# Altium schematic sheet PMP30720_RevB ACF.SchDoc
size 431 x 279 mm; Date: Not shown in title block; ApprovedBy: Not shown in title block; CheckedBy: Not shown in title block; Author: Not shown in title block; CompanyName: Not shown in title block; Engineer: Not shown in title block; Organization: Not shown in title block; Address1: Not shown in title block; Address2: Not shown in title block; Address3: Not shown in title block; Address4: Not shown in title block; DocumentNumber: 1; Revision: Use project parameter SCH_Rev; SheetNumber: 1; SheetTotal: 1; PageSetup: Record=PageOptions¦CenterHorizontal=True¦CenterVertical=True¦PrintScale=1.00¦XCorrection=1.00¦YCorrection=1.00¦PrintKind=0¦BorderSize=5000000¦LeftOffset=0¦BottomOffset=0¦Orientation=2¦PaperLength=1000¦PaperWidth=1000¦Scale=100¦PaperSource=15¦PrintQuality=600¦MediaType=1¦DitherType=10¦PaperKind=Letter¦PrintScaleMode=1
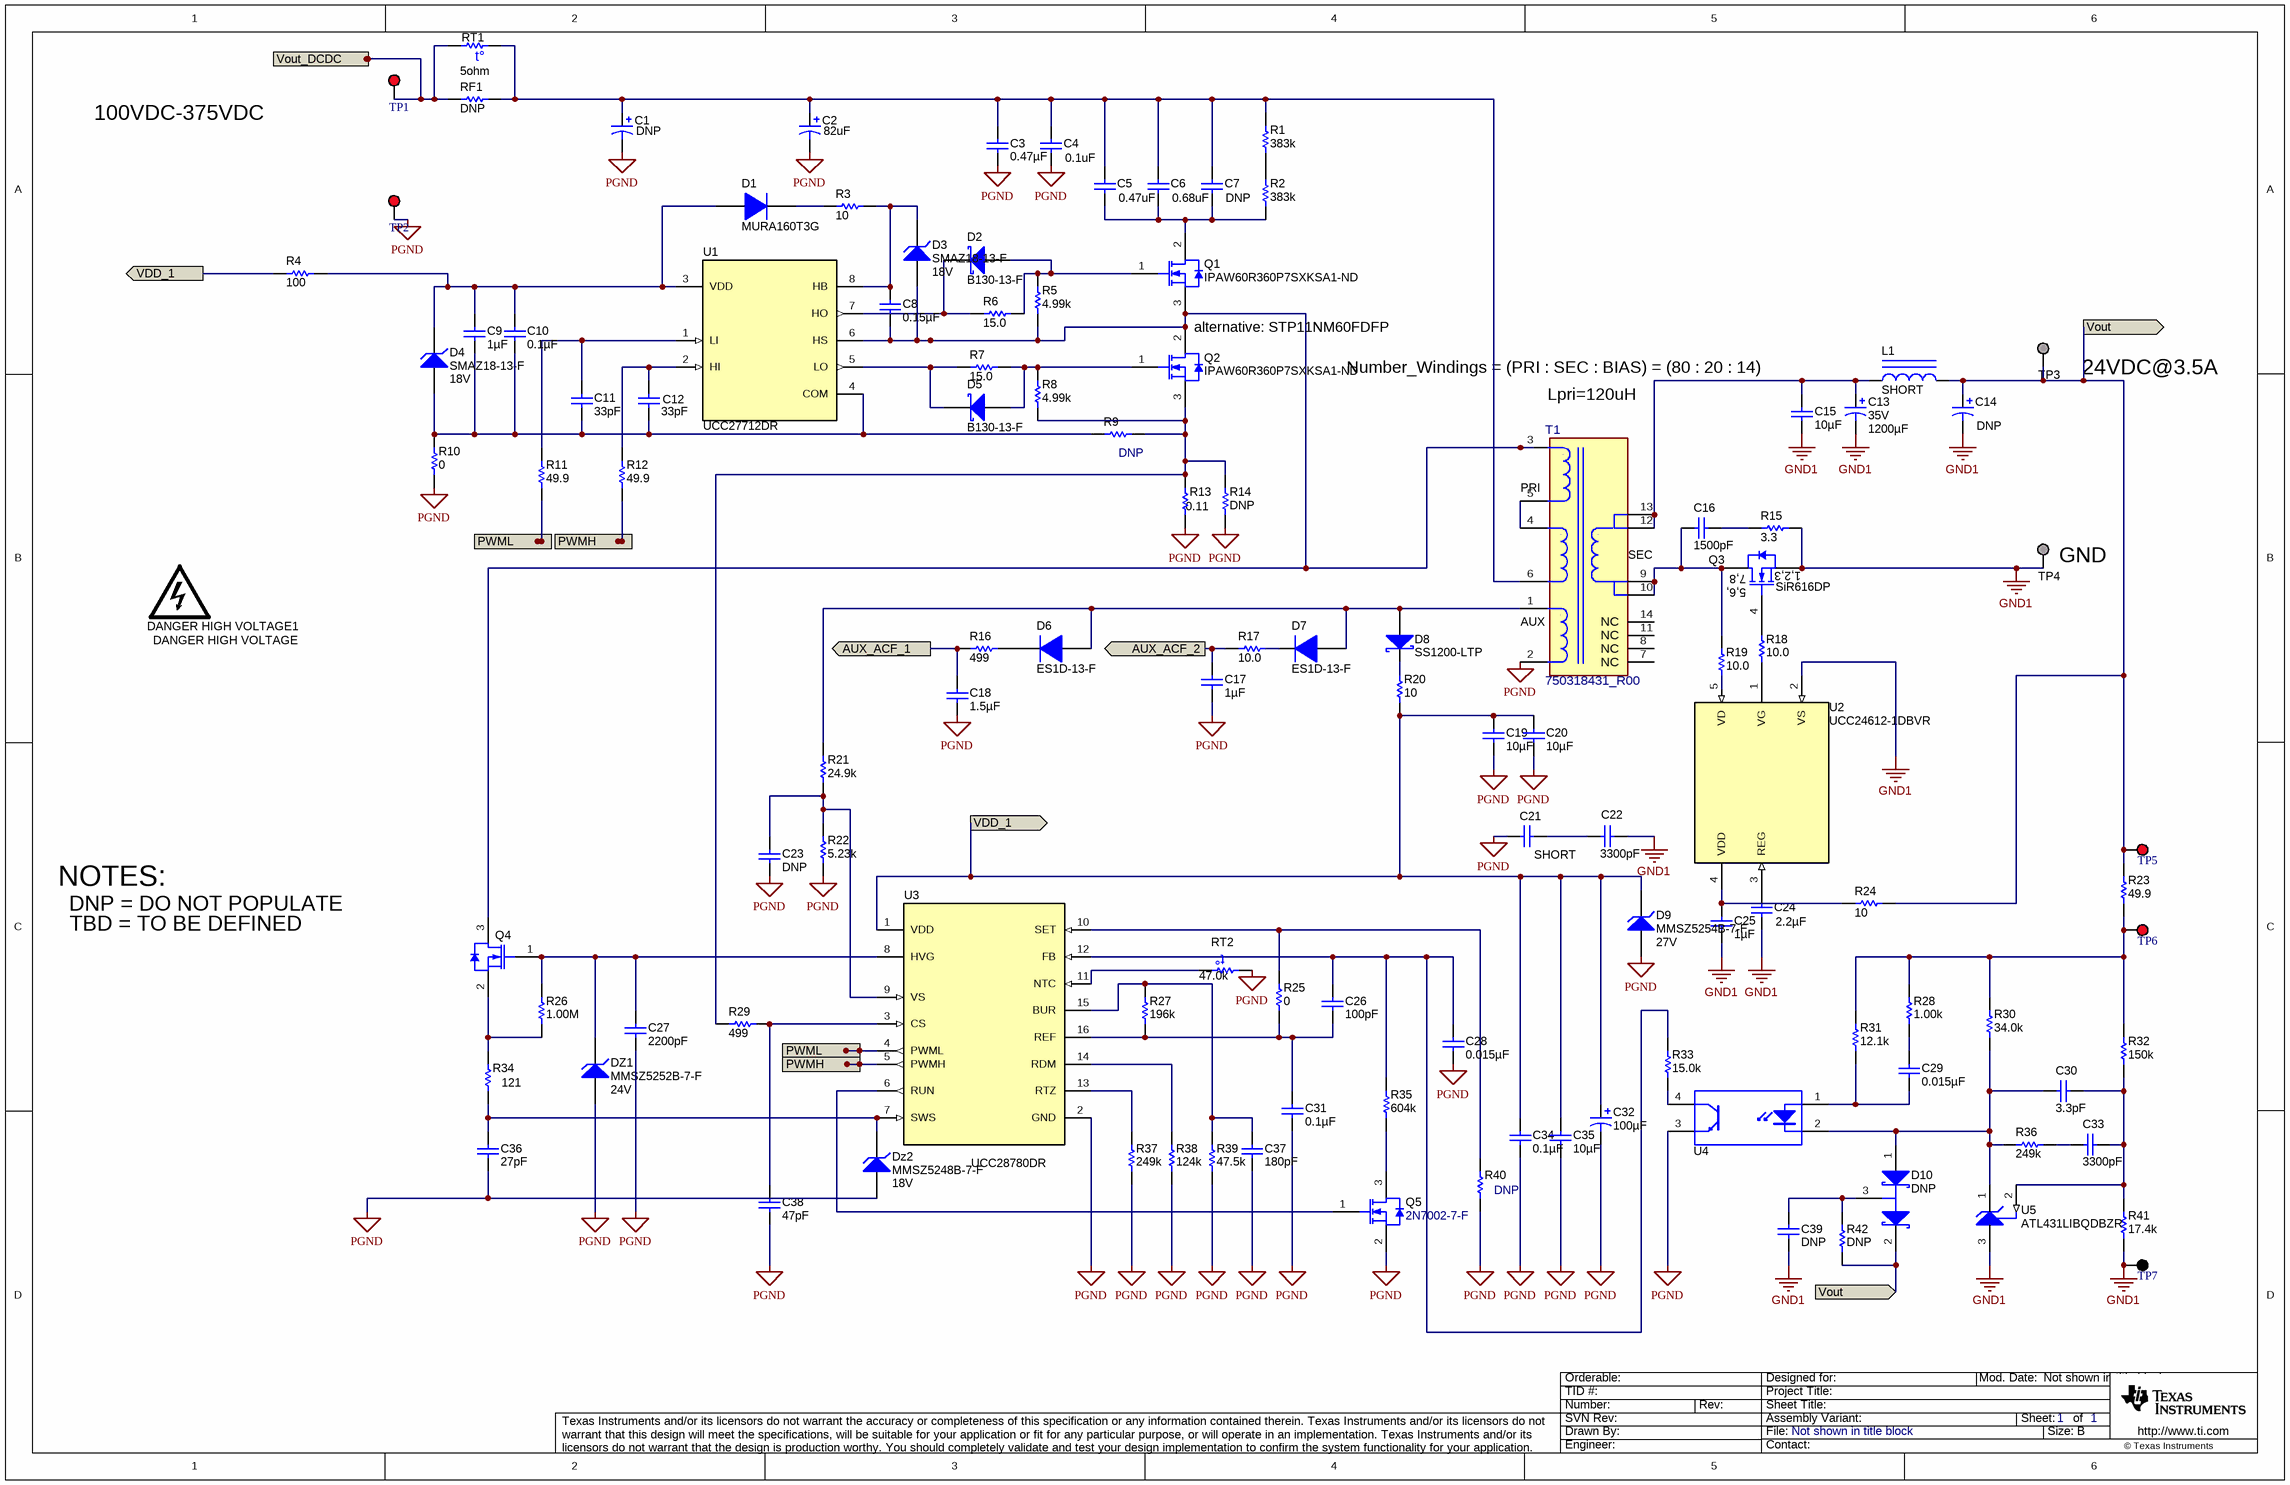
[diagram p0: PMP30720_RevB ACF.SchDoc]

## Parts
C1  value DNP  [CAPPR7.5-18x31.5]  (hidden comment: 450BXW82MEFR18X30)
C2  value 82uF  [CAPPR7.5-18x31.5]  (hidden comment: 450BXW82MEFR18X30)
C3  ValueDisplayed: 0.47µF  [1812_254]  (hidden comment: 1812Y5000474KXTWS2)
C4  ValueDisplayed: 0.1uF  [1206_190]  (hidden comment: C3216X7T2W104K160AA)
C5  value 0.47uF  [2220]  (hidden comment: GRM55DR72E474KW01L)
C6  value 0.68uF  [2220]  (hidden comment: DNP)
C7  value DNP  [2220]  (hidden comment: GRM55DR72E684KW01L)
C8  ValueDisplayed: 0.15µF  [0805_HV]  (hidden comment: C0805C154K5RACTU)
C9  ValueDisplayed: 1µF  [0805_HV]  (hidden comment: GRM21BR71H105KA12L)
C10  ValueDisplayed: 0.1µF  [0805_HV]  (hidden comment: GRM21BR71H104KA01L)
C11  ValueDisplayed: 33pF  [0603]  (hidden comment: GRM1885C1H330JA01D)
C12  ValueDisplayed: 33pF  [0603]  (hidden comment: GRM1885C1H330JA01D)
C13  VDC_V: 35V  ValueDisplayed: 1200µF  [Panasonic_1250x3000]  (hidden comment: EEU-FM1V122L)
C14  DNP  [CAPPR5-12.5x25]
C15  ValueDisplayed: 10µF  [1210_270]  (hidden comment: GRM32ER71H106KA12L)
C16  ValueDisplayed: 1500pF  [1206]  (hidden comment: GRM31BR72J152KW01L)
C17  ValueDisplayed: 1µF  [1206]  (hidden comment: GRM31MR71H105KA88L)
C18  ValueDisplayed: 1.5µF  [1206_180]  (hidden comment: C3216X7R1H155K160AB)
C19  ValueDisplayed: 10µF  [1210_280]  (hidden comment: C3225X7R1H106M250AC)
C20  ValueDisplayed: 10µF  [1210_280]  (hidden comment: C3225X7R1H106M250AC)
C21  SHORT  [KX_1000x700]
C22  ValueDisplayed: 3300pF  [KX_1000x700]  (hidden comment: DE1E3KX332MN4AP01F)
C23  DNP  [0603]
C24  ValueDisplayed: 2.2µF  [0805_HV]  (hidden comment: C2012X7R1H225K125AC)
C25  ValueDisplayed: 1µF  [0805_HV]  (hidden comment: GRM21BR71H105KA12L)
C26  ValueDisplayed: 100pF  [0603]  (hidden comment: GRM1885C1H101JA01D)
C27  ValueDisplayed: 2200pF  [0603]  (hidden comment: GRM188R71H222KA01D)
C28  ValueDisplayed: 0.015µF  [0603]  (hidden comment: GRM188R71H153KA01D)
C29  ValueDisplayed: 0.015µF  [0603]  (hidden comment: GRM188R71H153KA01D)
C30  ValueDisplayed: 3.3pF  [0603]  (hidden comment: 06035A3R3CAT2A)
C31  ValueDisplayed: 0.1µF  [0805_HV]  (hidden comment: GRM21BR71H104KA01L)
C32  ValueDisplayed: 100µF  [SM_RADIAL_D8]  (hidden comment: EEE-FK1V101XP)
C33  ValueDisplayed: 3300pF  [0603]  (hidden comment: GRM188R71H332KA01D)
C34  ValueDisplayed: 0.1µF  [0805_HV]  (hidden comment: GRM21BR71H104KA01L)
C35  ValueDisplayed: 10µF  [1210_270]  (hidden comment: GRM32ER71H106MA12)
C36  ValueDisplayed: 27pF  [0603]  (hidden comment: GRM1885C1H270JA01D)
C37  ValueDisplayed: 180pF  [0805_HV]  (hidden comment: GRM2165C1H181JA01D)
C38  ValueDisplayed: 47pF  [0603]  (hidden comment: GRM1885C1H470JA01D)
C39  DNP  [1206_180]
D1  MURA160T3G  [SMA]
D2  B130-13-F  [SMA]
D3  SMAZ18-13-F  value 18V  [SMA]
D4  SMAZ18-13-F  value 18V  [SMA]
D5  B130-13-F  [SMA]
D6  ES1D-13-F  [SMA]
D7  ES1D-13-F  [SMA]
D8  SS1200-LTP  [SMA]
D9  MMSZ5254B-7-F  value 27V  [SOD-123]
D10  DNP  [SOT-23]
DANGER_HIGH_VOLTAGE1  DANGER HIGH VOLTAGE  [IEC_HighVoltage_Small]  (no BOM)
DZ1  MMSZ5252B-7-F  value 24V  [SOD-123]
Dz2  MMSZ5248B-7-F  value 18V  [SOD-123]
L1  ValueDisplayed: SHORT  [WE-TI_5075]  (hidden comment: 7447462010)
Q1  IPAW60R360P7SXKSA1-ND  [TO-220AB]
Q2  IPAW60R360P7SXKSA1-ND  [TO-220AB]
Q3  PartNumber: SiR616DP  [PG-TDSON-8]  (hidden comment: SiR616)
Q4  BSS126 H6906  [SOT-23]  (value not drawn)
Q5  2N7002-7-F  [SOT-23]
R1  ValueDisplayed: 383k  [1206]  (hidden comment: CRCW1206383KFKEA)
R2  ValueDisplayed: 383k  [1206]  (hidden comment: CRCW1206383KFKEA)
R3  ValueDisplayed: 10  [0805_HV]  (hidden comment: CRCW080510R0JNEA)
R4  ValueDisplayed: 100  [1206]  (hidden comment: CRCW1206100RJNEA)
R5  ValueDisplayed: 4.99k  [0805_HV]  (hidden comment: CRCW08054K99FKEA)
R6  ValueDisplayed: 15.0  [0805_HV]  (hidden comment: CRCW080515R0FKEA)
R7  ValueDisplayed: 15.0  [0805_HV]  (hidden comment: CRCW080515R0FKEA)
R8  ValueDisplayed: 4.99k  [0805_HV]  (hidden comment: CRCW08054K99FKEA)
R9  DNP  [0805]
R10  ValueDisplayed: 0  [1206]  (hidden comment: CRCW12060000Z0EA)
R11  ValueDisplayed: 49.9  [0603]  (hidden comment: CRCW060349R9FKEA)
R12  ValueDisplayed: 49.9  [0603]  (hidden comment: CRCW060349R9FKEA)
R13  value 0.11  [1206]  (hidden comment: ERJ-8RSJR12V)
R14  DNP  [1206]
R15  ValueDisplayed: 3.3  [2512]  (hidden comment: CRCW25123R30JNEG)
R16  ValueDisplayed: 499  [1206]  (hidden comment: CRCW1206499RFKEA)
R17  ValueDisplayed: 10.0  [1206]  (hidden comment: CRCW120610R0FKEA)
R18  ValueDisplayed: 10.0  [0805_HV]  (hidden comment: CRCW080510R0FKEA)
R19  ValueDisplayed: 10.0  [0603]  (hidden comment: CRCW060310R0FKEA)
R20  ValueDisplayed: 10  [0805_HV]  (hidden comment: CRCW080510R0JNEA)
R21  ValueDisplayed: 24.9k  [0603]  (hidden comment: CRCW060324K9FKEA)
R22  ValueDisplayed: 5.23k  [0603]  (hidden comment: CRCW06035K23FKEA)
R23  ValueDisplayed: 49.9  [0603]  (hidden comment: CRCW060349R9FKEA)
R24  ValueDisplayed: 10  [0805_HV]  (hidden comment: CRCW080510R0JNEA)
R25  ValueDisplayed: 0  [0603]  (hidden comment: CRCW06030000Z0EA)
R26  ValueDisplayed: 1.00M  [0603]  (hidden comment: CRCW06031M00FKEA)
R27  ValueDisplayed: 196k  [0603]  (hidden comment: CRCW0603196KFKEA)
R28  ValueDisplayed: 1.00k  [0603]  (hidden comment: CRCW06031K00FKEA)
R29  ValueDisplayed: 499  [0603]  (hidden comment: CRCW0603499RFKEA)
R30  ValueDisplayed: 34.0k  [0603]  (hidden comment: CRCW060334K0FKEA)
R31  ValueDisplayed: 12.1k  [0603]  (hidden comment: RC0603FR-0712K1L)
R32  ValueDisplayed: 150k  [0603]  (hidden comment: CRCW0603150KFKEA)
R33  ValueDisplayed: 15.0k  [0603]  (hidden comment: CRCW060315K0FKEA)
R34  value 121  [0603]  (hidden comment: CRCW0603121RFKEA)
R35  ValueDisplayed: 604k  [0603]  (hidden comment: CRCW0603604KFKEA)
R36  ValueDisplayed: 249k  [0603]  (hidden comment: CRCW0603249KFKEA)
R37  ValueDisplayed: 249k  [0603]  (hidden comment: CRCW0603249KFKEA)
R38  ValueDisplayed: 124k  [0603]  (hidden comment: CRCW0603124KFKEA)
R39  ValueDisplayed: 47.5k  [0603]  (hidden comment: CRCW060347K5FKEA)
R40  DNP  [0603_HV]
R41  ValueDisplayed: 17.4k  [0603]  (hidden comment: CRCW060317K4FKEA)
R42  DNP  [0805_HV]
RF1  DNP  [2512]
RT1  value 5ohm  [S237]  (hidden comment: B57464S0509M000)
RT2  value 47.0k  [0603]  (hidden comment: NCP18WB473F10RB)
T1  750318431_R00  [FP-750318431_R00_PTH_14-MFG]
TP1  5000  [Keystone5000]  (value not drawn)
TP2  5000  [Keystone5000]  (value not drawn)
TP3  Suggest using a net name here  [Keystone1503-2]  (value not drawn)
TP4  Suggest using a net name here  [Keystone1503-2]  (value not drawn)
TP5  5000  [Keystone5000]  (value not drawn)
TP6  5000  [Keystone5000]  (value not drawn)
TP7  5001  [Keystone5001]  (value not drawn)
U1  UCC27712DR  [D0008A_N]
U2  UCC24612-1DBVR  [DBV0005A_N]
U3  UCC28780DR  [D0016A_N]
U4  FOD817AS  [N04C]  (value not drawn)
U5  ATL431LIBQDBZR  [DBZ0003A_N]

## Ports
AUX_ACF_1 (out), AUX_ACF_2 (out), PWMH (in), PWMH (out), PWML (in), PWML (out), VDD_1 (out), Vout (in), Vout (out), Vout_DCDC (in)

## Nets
GND1: C13.2(-) C14.2(-) C15.2 C22.1 C24.2 C25.2 C39.2 Q3.1(S) Q3.2(S) Q3.3(S) R15.2 R41.1 TP4.1 TP7.1 U2.2(VS) U5.3(ANODE)
PGND: C1.2(-) C2.2(-) C3.2 C4.2 C17.2 C18.2 C19.2 C20.2 C21.2 C23.2 C27.1 C28.2 C31.2 C32.2(-) C34.2 C35.2 C36.2 C37.2 C38.2 D9.2(A) DZ1.2(A) Dz2.2(A) Q5.2(S) R10.1 R13.1 R14.1 R22.1 R37.1 R38.1 R39.1 R40.2 RT2.1 T1.2 TP2.1 U3.2(GND) U4.3(E)
AUX_ACF_1: C18.1 R16.1 ; port AUX_ACF_1
AUX_ACF_2: C17.1 R17.1 ; port AUX_ACF_2
PWMH: U3.5(PWMH) ; port PWMH
PWML: U3.4(PWML) ; port PWML
VDD_1: C19.1 C20.1 C32.1(+) C34.1 C35.1 D9.1(K) R4.1 R20.1 U3.1(VDD) ; port VDD_1
Vout: C14.1(+) D10.2(K) L1.2 R23.2 R24.2 R42.1 TP3.1 TP5.1 ; port Vout
Vout_DCDC: RF1.1 RT1.1 TP1.1 ; port Vout_DCDC
NetC1_1: C1.1(+) C2.1(+) C3.1 C4.1 C5.1 C6.1 C7.1 R1.2 RF1.2 RT1.2 T1.6
NetC5_2: C5.2 C6.2 C7.2 Q1.2(D) R2.1
NetC8_1: C8.1 D3.1(K) R3.1 U1.8(HB)
NetC8_2: C8.2 D3.2(A) Q1.3(S) Q2.2(D) Q4.3(D) R5.1 T1.3 U1.6(HS)
NetC9_1: C9.1 C10.1 D1.2(A) D4.1(K) R4.2 U1.3(VDD)
NetC9_2: C9.2 C10.2 C11.2 C12.2 D4.2(A) R9.1 R10.2 U1.4(COM)
NetC11_1: C11.1 R11.2 U1.1(LI)
NetC12_1: C12.1 R12.2 U1.2(HI)
NetC13_1: C13.1(+) C15.1 L1.1 T1.12 T1.13
NetC16_1: C16.1 R15.1
NetC16_2: C16.2 Q3.5(D) Q3.6(D) Q3.7(D) Q3.8(D) Q3.9(D) R19.2 T1.9 T1.10
NetC21_1: C21.1 C22.2
NetC23_1: C23.1 R21.1 R22.2 U3.9(VS)
NetC24_1: C24.1 U2.3(REG)
NetC25_1: C25.1 R24.1 U2.4(VDD)
NetC26_1: C26.1 C28.1 R33.2 R35.2 U3.12(FB)
NetC26_2: C26.2 C31.1 R25.1 R27.1 U3.16(REF)
NetC27_2: C27.2 DZ1.1(K) Q4.1(G) R26.2 U3.8(HVG)
NetC29_1: C29.1 R28.1
NetC29_2: C29.2 R31.1 U4.1(A)
NetC30_1: C30.1 C33.1 R32.1 R41.2 U5.2(REF)
NetC30_2: C30.2 D10.1(A) R30.1 R36.1 U4.2(K) U5.1(CATHODE)
NetC33_2: C33.2 R36.2
NetC36_1: C36.1 Dz2.1(K) R34.1 U3.7(SWS)
NetC37_1: C37.1 R27.2 R39.2 U3.15(BUR)
NetC38_1: C38.1 R29.2 U3.3(CS)
NetC39_1: C39.1 D10.3(C) R42.2
NetD1_1: D1.1(K) R3.2
NetD2_1: D2.1(K) R6.2 U1.7(HO)
NetD2_2: D2.2(A) Q1.1(G) R5.2 R6.1
NetD5_1: D5.1(K) R7.2 U1.5(LO)
NetD5_2: D5.2(A) Q2.1(G) R7.1 R8.2
NetD6_1: D6.1(K) R16.2
NetD6_2: D6.2(A) D7.2(A) D8.2(A) R21.2 T1.1
NetD7_1: D7.1(K) R17.2
NetD8_1: D8.1(K) R20.2
NetQ2_3: Q2.3(S) R8.1 R9.2 R13.2 R14.2 R29.1
NetQ3_4: Q3.4(G) R18.2
NetQ4_2: Q4.2(S) R26.1 R34.2
NetQ5_1: Q5.1(G) U3.6(RUN)
NetQ5_3: Q5.3(D) R35.1
NetR1_1: R1.1 R2.2
NetR18_1: R18.1 U2.1(VG)
NetR19_1: R19.1 U2.5(VD)
NetR23_1: R23.1 R28.2 R30.2 R31.2 R32.2 TP6.1
NetR25_2: R25.2 R40.1 U3.10(SET)
NetR33_1: R33.1 U4.4(C)
NetR37_2: R37.2 U3.13(RTZ)
NetR38_2: R38.2 U3.14(RDM)
NetRT2_2: RT2.2 U3.11(NTC)
NetT1_4: T1.4 T1.5

Not connected (* = marked no-connect by the designer): R11 1; R12 1; T1 7(NC) 8(NC) 11(NC) 14(NC)

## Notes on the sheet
- 100VDC-375VDC
- alternative: STP11NM60FDFP
- (near C15) Number_Windings = (PRI : SEC : BIAS) = (80 : 20 : 14)
- (near TP3) 24VDC@3.5A
- (near T1) Lpri=120uH
- (near T1) PRI
- (near T1) SEC
- (near TP4) GND
- (near T1) AUX
- NOTES:
- DNP = DO NOT POPULATE
- TBD = TO BE DEFINED

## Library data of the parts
C1 C2 = Capacitor_Polarized: CAP, [Technology], 82uF, 450V, +/-xx%, xxOhm ESR, [MountType]; Manufacturer: Used in BOM report; Polarized: Y; U/M: EA
C3 = 1812Y5000474KXTWS2: CAP, CERM, 0.47 µF, 500 V,+/- 10%, X7R, 1812; Manufacturer: Knowles Capacitors; Polarized: N; CompType: Capacitor; Value: 0.47uF; U/M: EA; Cap_F: 0.00000047; Tolerance_%: 10; VDC_V: 500; Value2: 500V; TaMin_C: -55; TaMax_C: 125; Cap_Case: 1812; SizeArea_mm2: 14.4; SizeAreaWB_mm2: 23.1; SizeX_mm: 4.5; SizeY_mm: 3.2; SizeZ_mm: 2.54; AEC Category: Q200; Green_Lifecycle: Not Set; Green_REACh: Incomplete
C4 = CMP-0008727-1: CAP, CERM, 0.1 uF, 450 V, +/- 10%, X7T, 1206_190; Manufacturer: TDK; TaMin_C: -55°C; Polarized: N; SizeAreaWB_mm2: 10.92; Value1: Unknown; U/M: EA; Value: 0.1uF; TaMax_C: 125°C; SizeZ_mm: 1.9; SizeX_mm: 3.2; SizeY_mm: 1.6; Cap_Case: 1206; Value2: 450V; SizeArea_mm2: 5.12; Cap_F: 100nF; AEC Category: Q200
C5 = GRM55DR72E474KW01L: CAP, CERM, 0.47 µF, 250 V,+/- 10%, X7R, 2220; Manufacturer: MuRata; Polarized: N; CompType: Capacitor; ValueDisplayed: 0.47µF; U/M: EA; Cap_F: 0.00000047; Tolerance_%: 10; VDC_V: 250; Value2: 250V; TaMin_C: -55; TaMax_C: 125; SizeArea_mm2: 28.5; SizeAreaWB_mm2: 53.9; SizeX_mm: 5.7; SizeY_mm: 5; SizeZ_mm: 1.35; AEC Category: Q200
C6 C7 = GRM55DR72E474KW01L: CAP, CERM, 0.68 µF, 250 V,+/- 10%, X7R, 2220; Manufacturer: MuRata; Polarized: N; CompType: Capacitor; U/M: EA; Cap_F: 0.00000047; Tolerance_%: 10; VDC_V: 250; Value2: 250V; TaMin_C: -55; TaMax_C: 125; SizeArea_mm2: 28.5; SizeAreaWB_mm2: 53.9; SizeX_mm: 5.7; SizeY_mm: 5; SizeZ_mm: 1.35; AEC Category: Q200
C8 = C0805C154K5RACTU: CAP, CERM, 0.15 µF, 50 V,+/- 10%, X7R, 0805; Manufacturer: Kemet; Polarized: N; CompType: Capacitor; Value: 0.15uF; U/M: EA; Cap_F: 0.00000015; Tolerance_%: 10; ESR_ohm: 0.054; Value1: 0.054 ohm; VDC_V: 50; Value2: 50V; IRMS_A: 2.09; TaMin_C: -55; TaMax_C: 125; Cap_Case: 0805; SizeArea_mm2: 2.5; SizeAreaWB_mm2: 6.75; SizeX_mm: 2; SizeY_mm: 1.25; SizeZ_mm: 1.45; AEC Category: Q200; Green_Lifecycle: Active; Green_REACh: Passed
C9 C25 = GRM21BR71H105KA12L: CAP, CERM, 1 µF, 50 V,+/- 10%, X7R, 0805; Manufacturer: MuRata; Polarized: N; CompType: Capacitor; Value: 1uF; U/M: EA; Cap_F: 0.000001; Tolerance_%: 10; VDC_V: 50; Value2: 50V; TaMin_C: -55; TaMax_C: 125; Cap_Case: 0805; SizeArea_mm2: 2.5; SizeAreaWB_mm2: 6.75; SizeX_mm: 2; SizeY_mm: 1.25; SizeZ_mm: 1.45; AEC Category: Q200; Green_Lifecycle: Active; Green_REACh: Passed
C10 C31 C34 = GRM21BR71H104KA01L: CAP, CERM, 0.1 µF, 50 V,+/- 10%, X7R, 0805; Manufacturer: MuRata; Polarized: N; CompType: Capacitor; Value: 0.1uF; U/M: EA; Cap_F: 0.0000001; Tolerance_%: 10; VDC_V: 50; Value2: 50V; TaMin_C: -55; TaMax_C: 125; Cap_Case: 0805; SizeArea_mm2: 2.5; SizeAreaWB_mm2: 6.75; SizeX_mm: 2; SizeY_mm: 1.25; SizeZ_mm: 1.45; AEC Category: Q200; Green_Lifecycle: Active; Green_REACh: Passed
C11 C12 = GRM1885C1H330JA01D: CAP, CERM, 33 pF, 50 V,+/- 5%, C0G/NP0, 0603; Manufacturer: MuRata; Polarized: N; CompType: Capacitor; Value: 33pF; U/M: EA; Cap_F: 0.000000000033; Tolerance_%: 5; VDC_V: 50; Value2: 50V; TaMin_C: -55; TaMax_C: 125; SizeArea_mm2: 1.28; SizeAreaWB_mm2: 4.68; SizeX_mm: 1.6; SizeY_mm: 0.8; SizeZ_mm: 1; AEC Category: Q200; Green_Lifecycle: Active; Green_REACh: Passed
C13 = CMP-0079558-1: CAP, AL, 1200 µF, 35 V, +/- 20%, TH; Manufacturer: Panasonic; Cap_F: 1.2mF; IRMS_A: 3.63A; SizeAreaWB_mm2: 210.25; SizeArea_mm2: 156.25; AEC Qualified: N; AEC Category: Q200; Value: 1200uF; TaMax_C: 105°C; SizeZ_mm: 32; Polarized: Y; TaMin_C: -40°C; SizeY_mm: 12.5; U/M: EA; CompType: Capacitor; Cap_Case: 12.5x30mm
C14 = Capacitor_Polarized: CAP, [Technology], xxxF, xxV, +/-xx%, xxOhm ESR, [MountType]; Manufacturer: Used in BOM report; Polarized: Y; U/M: EA
C15 = GRM32ER71H106KA12L: CAP, CERM, 10 µF, 50 V,+/- 10%, X7R, 1210; Manufacturer: MuRata; Polarized: N; CompType: Capacitor; Value: 10uF; U/M: EA; Cap_F: 0.00001; Tolerance_%: 10; VDC_V: 50; Value2: 50V; TaMin_C: -55; TaMax_C: 125; Cap_Case: 1210; SizeArea_mm2: 8; SizeAreaWB_mm2: 14.7; SizeX_mm: 3.2; SizeY_mm: 2.5; SizeZ_mm: 2.7; AEC Category: Q200; Green_Lifecycle: Active; Green_REACh: Passed
C16 = GRM31BR72J152KW01L: CAP, CERM, 1500 pF, 630 V,+/- 10%, X7R, 1206; Manufacturer: MuRata; Polarized: N; CompType: Capacitor; Value: 1500pF; U/M: EA; Cap_F: 0.0000000015; Tolerance_%: 10; VDC_V: 630; Value2: 630V; TaMin_C: -55; TaMax_C: 125; SizeArea_mm2: 5.12; SizeAreaWB_mm2: 10.92; SizeX_mm: 3.2; SizeY_mm: 1.6; SizeZ_mm: 1.35; AEC Category: Q200
C17 = GRM31MR71H105KA88L: CAP, CERM, 1 µF, 50 V,+/- 10%, X7R, 1206; Manufacturer: MuRata; Polarized: N; CompType: Capacitor; Value: 1uF; U/M: EA; Cap_F: 0.000001; Tolerance_%: 10; VDC_V: 50; Value2: 50V; TaMin_C: -55; TaMax_C: 125; SizeArea_mm2: 5.12; SizeAreaWB_mm2: 10.92; SizeX_mm: 3.2; SizeY_mm: 1.6; SizeZ_mm: 1.35; AEC Category: Q200; Green_Lifecycle: Active; Green_REACh: Passed
C18 = C3216X7R1H155K160AB: CAP, CERM, 1.5 µF, 50 V,+/- 10%, X7R, 1206; Manufacturer: TDK; Polarized: N; CompType: Capacitor; Value: 1.5uF; U/M: EA; Cap_F: 0.0000015; Tolerance_%: 10; ESR_ohm: 0.007741; Value1: 0.007741 ohm; VDC_V: 50; Value2: 50V; IRMS_A: 2.61033; TaMin_C: -55; TaMax_C: 125; Cap_Case: 1206; SizeArea_mm2: 5.12; SizeAreaWB_mm2: 10.92; SizeX_mm: 3.2; SizeY_mm: 1.6; SizeZ_mm: 1.8; AEC Category: Q200
C19 C20 = C3225X7R1H106M250AC: CAP, CERM, 10 µF, 50 V,+/- 20%, X7R, 1210; Manufacturer: TDK; Polarized: N; CompType: Capacitor; Value: 10uF; U/M: EA; Cap_F: 0.00001; Tolerance_%: 20; VDC_V: 50; Value2: 50V; TaMin_C: -55; TaMax_C: 125; Cap_Case: 1210; SizeArea_mm2: 8; SizeAreaWB_mm2: 14.7; SizeX_mm: 3.2; SizeY_mm: 2.5; SizeZ_mm: 2.8; AEC Category: Q200; Green_Lifecycle: Active; Green_REACh: Passed
C21 = DE1E3KX332MN4AP01F: CAP, CERM, 3300 pF, X1 250 VAC/Y1 300 VAC, +/- 20%, E, D10xT7mm; Manufacturer: MuRata; Polarized: N; CompType: Capacitor; U/M: EA; Cap_F: 0.0000000033; Tolerance_%: 20; TaMin_C: -40; TaMax_C: 125; Cap_Case: 10x7mm; SizeArea_mm2: 70; SizeAreaWB_mm2: 108; SizeX_mm: 10; SizeY_mm: 7; SizeZ_mm: 13; AEC Category: Q200; AC_Safety: X1Y1; VAC_X: 250; VAC_Y: 300
C22 = DE1E3KX332MN4AP01F: CAP, CERM, 3300 pF, X1 250 VAC/Y1 300 VAC, +/- 20%, E, D10xT7mm; Manufacturer: MuRata; Polarized: N; CompType: Capacitor; Value: 3300pF; U/M: EA; Cap_F: 0.0000000033; Tolerance_%: 20; TaMin_C: -40; TaMax_C: 125; Cap_Case: 10x7mm; SizeArea_mm2: 70; SizeAreaWB_mm2: 108; SizeX_mm: 10; SizeY_mm: 7; SizeZ_mm: 13; AEC Category: Q200; AC_Safety: X1Y1; VAC_X: 250; VAC_Y: 300
C23 = 06035A3R3CAT2A: CAP, CERM, 3.3 pF, 50 V,+/- 8%, C0G/NP0, 0603; Manufacturer: AVX; Polarized: N; CompType: Capacitor; U/M: EA; Cap_F: 0.0000000000033; Tolerance_%: 8; ESR_ohm: 0.792; Value1: 0.792 ohm; VDC_V: 50; Value2: 50V; TaMin_C: -55; TaMax_C: 125; SizeArea_mm2: 1.28; SizeAreaWB_mm2: 4.68; SizeX_mm: 1.6; SizeY_mm: 0.8; SizeZ_mm: 1; AEC Category: Q200; Green_Lifecycle: Not Set; Green_REACh: Incomplete
C24 = C2012X7R1H225K125AC: CAP, CERM, 2.2 µF, 50 V,+/- 10%, X7R, 0805; Manufacturer: TDK; Polarized: N; CompType: Capacitor; Value: 2.2uF; U/M: EA; Cap_F: 0.0000022; Tolerance_%: 10; ESR_ohm: 0.00366; Value1: 0.00366 ohm; VDC_V: 50; Value2: 50V; IRMS_A: 3.41207; TaMin_C: -55; TaMax_C: 125; Cap_Case: 0805; SizeArea_mm2: 2.5; SizeAreaWB_mm2: 6.75; SizeX_mm: 2; SizeY_mm: 1.25; SizeZ_mm: 1.45; AEC Category: Q200; Green_Lifecycle: Active; Green_REACh: Passed
C26 = GRM1885C1H101JA01D: CAP, CERM, 100 pF, 50 V,+/- 5%, C0G/NP0, 0603; Manufacturer: MuRata; Polarized: N; CompType: Capacitor; Value: 100pF; U/M: EA; Cap_F: 0.0000000001; Tolerance_%: 5; VDC_V: 50; Value2: 50V; TaMin_C: -55; TaMax_C: 125; SizeArea_mm2: 1.28; SizeAreaWB_mm2: 4.68; SizeX_mm: 1.6; SizeY_mm: 0.8; SizeZ_mm: 1; AEC Category: Q200; Green_Lifecycle: Active; Green_REACh: Passed
C27 = GRM188R71H222KA01D: CAP, CERM, 2200 pF, 50 V,+/- 10%, X7R, 0603; Manufacturer: MuRata; Polarized: N; CompType: Capacitor; Value: 2200pF; U/M: EA; Cap_F: 0.0000000022; Tolerance_%: 10; VDC_V: 50; Value2: 50V; TaMin_C: -55; TaMax_C: 125; SizeArea_mm2: 1.28; SizeAreaWB_mm2: 4.68; SizeX_mm: 1.6; SizeY_mm: 0.8; SizeZ_mm: 1; AEC Category: Q200; Green_Lifecycle: Active; Green_REACh: Passed
C28 C29 = GRM188R71H153KA01D: CAP, CERM, 0.015 µF, 50 V,+/- 10%, X7R, 0603; Manufacturer: MuRata; Polarized: N; CompType: Capacitor; Value: 0.015uF; U/M: EA; Cap_F: 0.000000015; Tolerance_%: 10; VDC_V: 50; Value2: 50V; TaMin_C: -55; TaMax_C: 125; SizeArea_mm2: 1.28; SizeAreaWB_mm2: 4.68; SizeX_mm: 1.6; SizeY_mm: 0.8; SizeZ_mm: 1; AEC Category: Q200; Green_Lifecycle: Active; Green_REACh: Passed
C30 = 06035A3R3CAT2A: CAP, CERM, 3.3 pF, 50 V,+/- 8%, C0G/NP0, 0603; Manufacturer: AVX; Polarized: N; CompType: Capacitor; Value: 3.3pF; U/M: EA; Cap_F: 0.0000000000033; Tolerance_%: 8; ESR_ohm: 0.792; Value1: 0.792 ohm; VDC_V: 50; Value2: 50V; TaMin_C: -55; TaMax_C: 125; SizeArea_mm2: 1.28; SizeAreaWB_mm2: 4.68; SizeX_mm: 1.6; SizeY_mm: 0.8; SizeZ_mm: 1; AEC Category: Q200; Green_Lifecycle: Not Set; Green_REACh: Incomplete
C32 = EEE-FK1V101XP: CAP, AL, 100 µF, 35 V, +/- 20%, 0.34 ohm, AEC-Q200 Grade 2, SMD; Manufacturer: Panasonic; Polarized: Y; CompType: Capacitor; Value: 100uF; U/M: EA; Cap_F: 0.0001; Tolerance_%: 20; VDC_V: 35; Value2: 35V; ESR_ohm: 0.34; IRMS_A: 0.28; TaMin_C: -55; TaMax_C: 105; Cap_Case: D8; SizeAreaWB_mm2: 84.28; SizeArea_mm2: 51.48; SizeX_mm: 7.8; SizeY_mm: 6.6; SizeZ_mm: 7.7; AEC Category: Q200; AEC Grade: 2; Green_Lifecycle: Active; Green_REACh: Passed
C33 = GRM188R71H332KA01D: CAP, CERM, 3300 pF, 50 V,+/- 10%, X7R, 0603; Manufacturer: MuRata; Polarized: N; CompType: Capacitor; Value: 3300pF; U/M: EA; Cap_F: 0.0000000033; Tolerance_%: 10; VDC_V: 50; Value2: 50V; TaMin_C: -55; TaMax_C: 125; SizeArea_mm2: 1.28; SizeAreaWB_mm2: 4.68; SizeX_mm: 1.6; SizeY_mm: 0.8; SizeZ_mm: 1; AEC Category: Q200; Green_Lifecycle: Active; Green_REACh: Passed
C35 = GRM32ER71H106MA12: CAP, CERM, 10 µF, 50 V,+/- 20%, X7R, 1210; Manufacturer: MuRata; Polarized: N; CompType: Capacitor; Value: 10uF; U/M: EA; Cap_F: 0.00001; Tolerance_%: 20; VDC_V: 50; Value2: 50V; TaMin_C: -55; TaMax_C: 125; Cap_Case: 1210; SizeArea_mm2: 8; SizeAreaWB_mm2: 14.7; SizeX_mm: 3.2; SizeY_mm: 2.5; SizeZ_mm: 2.7; AEC Category: Q200
C36 = GRM1885C1H270JA01D: CAP, CERM, 27 pF, 50 V,+/- 5%, C0G/NP0, 0603; Manufacturer: MuRata; Polarized: N; CompType: Capacitor; Value: 27pF; U/M: EA; Cap_F: 0.000000000027; Tolerance_%: 5; VDC_V: 50; Value2: 50V; TaMin_C: -55; TaMax_C: 125; SizeArea_mm2: 1.28; SizeAreaWB_mm2: 4.68; SizeX_mm: 1.6; SizeY_mm: 0.8; SizeZ_mm: 1; AEC Category: Q200; Green_Lifecycle: Active; Green_REACh: Passed
C37 = GRM2165C1H181JA01D: CAP, CERM, 180 pF, 50 V,+/- 5%, C0G/NP0, 0805; Manufacturer: MuRata; Polarized: N; CompType: Capacitor; Value: 180pF; U/M: EA; Cap_F: 0.00000000018; Tolerance_%: 5; VDC_V: 50; Value2: 50V; TaMin_C: -55; TaMax_C: 125; Cap_Case: 0805; SizeArea_mm2: 2.5; SizeAreaWB_mm2: 6.75; SizeX_mm: 2; SizeY_mm: 1.25; SizeZ_mm: 1.45; AEC Category: Q200
C38 = GRM1885C1H470JA01D: CAP, CERM, 47 pF, 50 V,+/- 5%, C0G/NP0, 0603; Manufacturer: MuRata; Polarized: N; CompType: Capacitor; Value: 47pF; U/M: EA; Cap_F: 0.000000000047; Tolerance_%: 5; VDC_V: 50; Value2: 50V; TaMin_C: -55; TaMax_C: 125; SizeArea_mm2: 1.28; SizeAreaWB_mm2: 4.68; SizeX_mm: 1.6; SizeY_mm: 0.8; SizeZ_mm: 1; AEC Category: Q200; Green_Lifecycle: Active; Green_REACh: Passed
C39 = GRM31CR71H225KA88L: CAP, CERM, 2.2 µF, 50 V,+/- 10%, X7R, 1206; Manufacturer: MuRata; Polarized: N; CompType: Capacitor; U/M: EA; Cap_F: 0.0000022; Tolerance_%: 10; VDC_V: 50; Value2: 50V; TaMin_C: -55; TaMax_C: 125; Cap_Case: 1206; SizeArea_mm2: 5.12; SizeAreaWB_mm2: 10.92; SizeX_mm: 3.2; SizeY_mm: 1.6; SizeZ_mm: 1.8; AEC Category: Q200; Green_Lifecycle: Active; Green_REACh: Passed
D1 = MURA160T3G: Diode, Ultrafast, 600 V, 1 A, AEC-Q101, SMA; Manufacturer: ON Semiconductor; U/M: EA; Vf_V: 1.05; Value: 600V; Value1: 1A; Value2: 1.05V; Io_A: 1; Vr_V: 600; TJmax_C: 175; SizeAreaWB_mm2: 37.3428; SizeArea_mm2: 16.3228; SizeX_mm: 5.59; SizeY_mm: 2.92; SizeZ_mm: 2.87; AEC Category: Q101; AEC Qualified: Y; Green_Lifecycle: Active; Green_REACh: Passed
D2 D5 = B130-13-F: Diode, Schottky, 30 V, 1 A, SMA; Manufacturer: Diodes Inc.; U/M: EA; Vf_V: 0.5; Value: 30V; Value1: 1A; Value2: 0.5V; Io_A: 1; Vr_V: 30; TJmax_C: 150; RJC_CperW: 20; SizeAreaWB_mm2: 37.3428; SizeArea_mm2: 16.3228; SizeX_mm: 5.59; SizeY_mm: 2.92; SizeZ_mm: 2.87; AEC Category: Q101; Green_Lifecycle: Not Set; Green_REACh: Incomplete
D3 D4 = SMAZ18-13-F: Diode, Zener, 18 V, 1 W, AEC-Q101, SMA; Manufacturer: Diodes Inc.; SymbolCreator: a0412235; U/M: EA; Power_W: 1; Vz_V: 18; Value1: 1W; RJA_CperW: 125; SizeAreaWB_mm2: 37.3428; SizeArea_mm2: 16.3228; SizeX_mm: 5.59; SizeY_mm: 2.92; SizeZ_mm: 2.87; AEC Category: Q101; AEC Qualified: Y; Green_Lifecycle: Active; Green_REACh: Passed
D6 D7 = ES1D-13-F: Diode, Ultrafast, 200 V, 1 A, SMA; Manufacturer: Diodes Inc.; U/M: EA; Vf_V: 0.92; Value: 200V; Value1: 1A; Value2: 0.92V; Io_A: 1; Vr_V: 200; TJmax_C: 150; RJC_CperW: 25; SizeAreaWB_mm2: 37.3428; SizeArea_mm2: 16.3228; SizeX_mm: 5.59; SizeY_mm: 2.92; SizeZ_mm: 2.87; AEC Category: Q101; Green_Lifecycle: Active; Green_REACh: Passed
D8 = SS1200-LTP: Diode, Schottky, 200 V, 1 A, SMA; Manufacturer: Micro Commercial Components; U/M: EA; Vf_V: 0.92; Value: 200V; Value1: 1A; Value2: 0.92V; Io_A: 1; Vr_V: 200; TJmax_C: 150; SizeAreaWB_mm2: 37.3428; SizeArea_mm2: 16.3228; SizeX_mm: 5.59; SizeY_mm: 2.92; SizeZ_mm: 2.87; AEC Category: Q101; AEC Qualified: N
D9 = MMSZ5254B-7-F: Diode, Zener, 27 V, 500 mW, SOD-123; Manufacturer: Diodes Inc.; SymbolCreator: a0412235; U/M: EA; Power_W: 0.5; Vz_V: 27; Value1: 0.5W; RJA_CperW: 350; SizeAreaWB_mm2: 13.095; SizeArea_mm2: 6.545; SizeX_mm: 3.85; SizeY_mm: 1.7; SizeZ_mm: 1.35; AEC Category: Q101
D10 = BAT54S-7-F: Diode, Schottky, 30 V, 0.2 A, SOT-23; Manufacturer: Diodes Inc.; U/M: EA; Vf_V: 0.65; Value1: 0.2A; Value2: 0.65V; Io_A: 0.2; Vr_V: 30; TJmax_C: 125; SizeAreaWB_mm2: 14; SizeArea_mm2: 7.5; SizeX_mm: 2.5; SizeY_mm: 3; SizeZ_mm: 1.1; AEC Category: Q101; Green_Lifecycle: Active; Green_REACh: Passed
DANGER_HIGH_VOLTAGE1 = IEC_HighVoltage: IEC 61010-1 High Voltage Warning; SymbolCreator: a0412235
DZ1 = MMSZ5252B-7-F: Diode, Zener, 24 V, 500 mW, SOD-123; Manufacturer: Diodes Inc.; U/M: EA; Power_W: 0.5; Vz_V: 24; Value1: 0.5W; RJA_CperW: 350; SizeAreaWB_mm2: 13.095; SizeArea_mm2: 6.545; SizeX_mm: 3.85; SizeY_mm: 1.7; SizeZ_mm: 1.35; AEC Category: Q101; SymbolCreator: a0412235
Dz2 = MMSZ5248B-7-F: Diode, Zener, 18 V, 500 mW, SOD-123; Manufacturer: Diodes Inc.; SymbolCreator: a0412235; U/M: EA; Power_W: 0.5; Vz_V: 18; Value1: 0.5W; RJA_CperW: 350; SizeAreaWB_mm2: 13.095; SizeArea_mm2: 6.545; SizeX_mm: 3.85; SizeY_mm: 1.7; SizeZ_mm: 1.35; AEC Category: Q101; Green_Lifecycle: Active; Green_REACh: Passed
L1 = CMP-0064179-1: Inductor, Unshielded Drum Core, Ferrite, 1 uH, 8 A, 0.006 ohm, TH; Manufacturer: Wurth Elektronik; Isat: 8A @ 10% inductance drop; Irms: 8.5A @ 40C rise; Green_Lifecycle: Active; SizeAreaWB_mm2: 64; DCR_ohm: 6m; Green_REACh: Passed; Value: 1uH; Imax_A: 8A; SizeZ_mm: 8.5; SizeX_mm: 6; SizeArea_mm2: 36; Ind_H: 1µH; AEC Category: Q200
Q1 Q2 = MOSFET_N_D2G1S3: MOSFET, N-CH, 650V, xxxA, [PackageReference]; Manufacturer: Infineon; U/M: EA
Q3 = CMP-0079124-1: MOSFET, N-CH, 200 V, PG-TDSON-8; Alternate Manufacturer: None; ChType: N; QgTyp_nC: 22; SizeAreaWB_mm2: 55.131; SizeArea_mm2: 29.351; IdsMax_A: 35A; VdsMax_V: 200V; Vgs_V: 20V; AEC Category: Q101; Value: 200V; SizeZ_mm: 1.12; SizeY_mm: 4.9; U/M: EA; Value1: ? ohm; SizeX_mm: 5.99
Q4 = BSS126 H6906: MOSFET, N-CH, 600 V, 0.021 A, AEC-Q101, SOT-23; Manufacturer: Infineon Technologies; Alternate Manufacturer: None; SymbolCreator: a0412235; U/M: EA; ChType: N; Value: 600V; VdsMax_V: 600; Value1: ? ohm; Value2: 1.4 nC; QgTyp_nC: 1.4; Vgs_V: 20; IdsMax_A: 0.021; SizeAreaWB_mm2: 14; SizeArea_mm2: 7.5; SizeX_mm: 2.5; SizeY_mm: 3; SizeZ_mm: 1.1; AEC Category: Q101; AEC Qualified: Y
Q5 = CMP-0000769-1: MOSFET, N-CH, 60 V, 0.17 A, SOT-23; Alternate Manufacturer: None; Manufacturer: Diodes Inc.; SizeZ_mm: 1.1; ChType: N; Value2: 223 nC; Value1: 7; VdsMax_V: 60V; SizeX_mm: 2.5; SizeY_mm: 3; Vgs_V: 20V; Value: 60V; Rdson45_ohm: 7.5; AEC Category: Q101; IdsMax_A: 170mA; SizeAreaWB_mm2: 14; U/M: EA; QgTyp_nC: 223
R1 R2 = CRCW1206383KFKEA: RES, 383 k, 1%, 0.25 W, 1206; Manufacturer: Vishay-Dale; CompType: Resistor; Value: 383k; Res_ohm: 383000; Tolerance_%: 1; Power_W: 0.25; Value2: 0.25W; VDC_V: 200; TempCo: 100 ppm/C; SizeArea_mm2: 5.12; SizeX_mm: 3.2; SizeY_mm: 1.6; SizeZ_mm: 1.35; EIA_Code: E96; U/M: EA; AEC Category: Q200
R3 R20 R24 = CRCW080510R0JNEA: RES, 10, 5%, 0.125 W, 0805; Manufacturer: Vishay-Dale; CompType: Resistor; Value: 10; Value_Code: 10R0; Tolerance_%: 5; Power_W: 0.125; Value2: 0.125W; VDC_V: 150; TempCo: 200 ppm/C; SizeArea_mm2: 2.5; SizeX_mm: 2; SizeY_mm: 1.25; SizeZ_mm: 1.45; EIA_Code: E24; U/M: EA; AEC Category: Q200; Green_Lifecycle: Active; Green_REACh: Passed
R4 = CRCW1206100RJNEA: RES, 100, 5%, 0.25 W, 1206; Manufacturer: Vishay-Dale; CompType: Resistor; Value: 100; Value_Code: 100R; Tolerance_%: 5; Power_W: 0.25; Value2: 0.25W; VDC_V: 200; TempCo: 200 ppm/C; SizeArea_mm2: 5.12; SizeX_mm: 3.2; SizeY_mm: 1.6; SizeZ_mm: 1.35; EIA_Code: E24; U/M: EA; AEC Category: Q200
R5 R8 = CRCW08054K99FKEA: RES, 4.99 k, 1%, 0.125 W, 0805; Manufacturer: Vishay-Dale; CompType: Resistor; Value: 4.99k; Res_ohm: 4990; Value_Code: 4k99; Tolerance_%: 1; Power_W: 0.125; Value2: 0.125W; VDC_V: 150; TempCo: 100 ppm/C; SizeArea_mm2: 2.5; SizeX_mm: 2; SizeY_mm: 1.25; SizeZ_mm: 1.45; EIA_Code: E96; U/M: EA; AEC Category: Q200; Green_Lifecycle: Active; Green_REACh: Passed
R6 R7 = CRCW080515R0FKEA: RES, 15.0, 1%, 0.125 W, 0805; Manufacturer: Vishay-Dale; CompType: Resistor; Value: 15.0; Res_ohm: 15; Value_Code: 15R0; Tolerance_%: 1; Power_W: 0.125; Value2: 0.125W; VDC_V: 150; TempCo: 100 ppm/C; SizeArea_mm2: 2.5; SizeX_mm: 2; SizeY_mm: 1.25; SizeZ_mm: 1.45; EIA_Code: E96; U/M: EA; AEC Category: Q200
R9 R40 = Resistor: RES, xxx ohm, x%, xW, [PackageReference]; Manufacturer: Used in BOM report; U/M: EA
R10 = CRCW12060000Z0EA: RES, 0, 5%, 0.25 W, 1206; Manufacturer: Vishay-Dale; CompType: Resistor; Value: 0; Value_Code: 0000; Tolerance_%: 5; Power_W: 0.25; Value2: 0.25W; VDC_V: 200; TempCo: 200 ppm/C; SizeArea_mm2: 5.12; SizeX_mm: 3.2; SizeY_mm: 1.6; SizeZ_mm: 1.35; EIA_Code: E24; U/M: EA; AEC Category: Q200; Green_Lifecycle: Active; Green_REACh: Passed
R11 R12 R23 = CRCW060349R9FKEA: RES, 49.9, 1%, 0.1 W, 0603; Manufacturer: Vishay-Dale; CompType: Resistor; Value: 49.9; Value_Code: 49R9; Tolerance_%: 1; Power_W: 0.1; Value2: 0.1W; VDC_V: 75; TempCo: 100 ppm/C; SizeArea_mm2: 1.28; SizeX_mm: 1.6; SizeY_mm: 0.8; EIA_Code: E96; U/M: EA; AEC Category: Q200; Green_Lifecycle: Active; Green_REACh: Passed
R13 = ERJ-8RSJR12V: RES, 0.12, 5%, 0.25 W, 1206; Manufacturer: Panasonic; CompType: Resistor; ValueDisplayed: 0.12; Value_Code: R120; Tolerance_%: 5; Power_W: 0.25; Value2: 0.25W; TempCo: 250 ppm/C; SizeArea_mm2: 5.12; SizeX_mm: 3.2; SizeY_mm: 1.6; SizeZ_mm: 1.35; EIA_Code: E24; U/M: EA; AEC Category: Q200
R14 = ERJ-8RQFR33V: RES, 0.33, 1%, 0.25 W, 1206; Manufacturer: Panasonic; CompType: Resistor; Value: 0.33; Value_Code: R330; Tolerance_%: 1; Power_W: 0.25; Value2: 0.25W; TempCo: 250 ppm/C; SizeArea_mm2: 5.12; SizeX_mm: 3.2; SizeY_mm: 1.6; SizeZ_mm: 1.35; EIA_Code: E96; U/M: EA; AEC Category: Q200
R15 = CRCW25123R30JNEG: RES, 3.3, 5%, 1 W, AEC-Q200 Grade 0, 2512; Manufacturer: Vishay-Dale; CompType: Resistor; Value: 3.3; Value_Code: 3R30; Tolerance_%: 5; Power_W: 1; Value2: 1W; VDC_V: 500; TempCo: 200 ppm/C; SizeArea_mm2: 20.16; SizeX_mm: 6.3; SizeY_mm: 3.2; SizeZ_mm: 0.71; EIA_Code: E24; U/M: EA; AEC Category: Q200; AEC Qualified: Y; AEC Grade: 0
R16 = CRCW1206499RFKEA: RES, 499, 1%, 0.25 W, 1206; Manufacturer: Vishay-Dale; CompType: Resistor; Value: 499; Value_Code: 499R; Tolerance_%: 1; Power_W: 0.25; Value2: 0.25W; VDC_V: 200; TempCo: 100 ppm/C; SizeArea_mm2: 5.12; SizeX_mm: 3.2; SizeY_mm: 1.6; SizeZ_mm: 1.35; EIA_Code: E96; U/M: EA; AEC Category: Q200; Green_Lifecycle: Active; Green_REACh: Passed
R17 = CRCW120610R0FKEA: RES, 10.0, 1%, 0.25 W, 1206; Manufacturer: Vishay-Dale; CompType: Resistor; Value: 10.0; Res_ohm: 10; Value_Code: 10R0; Tolerance_%: 1; Power_W: 0.25; Value2: 0.25W; VDC_V: 200; TempCo: 100 ppm/C; SizeArea_mm2: 5.12; SizeX_mm: 3.2; SizeY_mm: 1.6; SizeZ_mm: 1.35; EIA_Code: E96; U/M: EA; AEC Category: Q200; Green_Lifecycle: Active; Green_REACh: Passed
R18 = CRCW080510R0FKEA: RES, 10.0, 1%, 0.125 W, 0805; Manufacturer: Vishay-Dale; CompType: Resistor; Value: 10.0; Res_ohm: 10; Value_Code: 10R0; Tolerance_%: 1; Power_W: 0.125; Value2: 0.125W; VDC_V: 150; TempCo: 100 ppm/C; SizeArea_mm2: 2.5; SizeX_mm: 2; SizeY_mm: 1.25; SizeZ_mm: 1.45; EIA_Code: E96; U/M: EA; AEC Category: Q200; Green_Lifecycle: Active; Green_REACh: Passed
R19 = CRCW060310R0FKEA: RES, 10.0, 1%, 0.1 W, 0603; Manufacturer: Vishay-Dale; CompType: Resistor; Value: 10.0; Res_ohm: 10; Value_Code: 10R0; Tolerance_%: 1; Power_W: 0.1; Value2: 0.1W; VDC_V: 75; TempCo: 100 ppm/C; SizeArea_mm2: 1.28; SizeX_mm: 1.6; SizeY_mm: 0.8; EIA_Code: E96; U/M: EA; AEC Category: Q200; Green_Lifecycle: Active; Green_REACh: Passed
R21 = CRCW060324K9FKEA: RES, 24.9 k, 1%, 0.1 W, 0603; Manufacturer: Vishay-Dale; CompType: Resistor; Value: 24.9k; Res_ohm: 24900; Value_Code: 24k9; Tolerance_%: 1; Power_W: 0.1; Value2: 0.1W; VDC_V: 75; TempCo: 100 ppm/C; SizeArea_mm2: 1.28; SizeX_mm: 1.6; SizeY_mm: 0.8; EIA_Code: E96; U/M: EA; AEC Category: Q200; Green_Lifecycle: Active; Green_REACh: Passed
R22 = CRCW06035K23FKEA: RES, 5.23 k, 1%, 0.1 W, 0603; Manufacturer: Vishay-Dale; CompType: Resistor; Value: 5.23k; Res_ohm: 5230; Value_Code: 5k23; Tolerance_%: 1; Power_W: 0.1; Value2: 0.1W; VDC_V: 75; TempCo: 100 ppm/C; SizeArea_mm2: 1.28; SizeX_mm: 1.6; SizeY_mm: 0.8; EIA_Code: E96; U/M: EA; AEC Category: Q200; Green_Lifecycle: Active; Green_REACh: Passed
R25 = CRCW06030000Z0EA: RES, 0, 5%, 0.1 W, 0603; Manufacturer: Vishay-Dale; CompType: Resistor; Value: 0; Value_Code: 0000; Tolerance_%: 5; Power_W: 0.1; Value2: 0.1W; VDC_V: 75; TempCo: 200 ppm/C; SizeArea_mm2: 1.28; SizeX_mm: 1.6; SizeY_mm: 0.8; SizeZ_mm: 1; EIA_Code: E24; U/M: EA; AEC Category: Q200; Green_Lifecycle: Active; Green_REACh: Passed
R26 = CRCW06031M00FKEA: RES, 1.00 M, 1%, 0.1 W, 0603; Manufacturer: Vishay-Dale; CompType: Resistor; Value: 1.00Meg; Res_ohm: 1000000; Value_Code: 1M00; Tolerance_%: 1; Power_W: 0.1; Value2: 0.1W; VDC_V: 75; TempCo: 100 ppm/C; SizeArea_mm2: 1.28; SizeX_mm: 1.6; SizeY_mm: 0.8; EIA_Code: E96; U/M: EA; AEC Category: Q200; Green_Lifecycle: Active; Green_REACh: Passed
R27 = CRCW0603196KFKEA: RES, 196 k, 1%, 0.1 W, 0603; Manufacturer: Vishay-Dale; CompType: Resistor; Value: 196k; Res_ohm: 196000; Tolerance_%: 1; Power_W: 0.1; Value2: 0.1W; VDC_V: 75; TempCo: 100 ppm/C; SizeArea_mm2: 1.28; SizeX_mm: 1.6; SizeY_mm: 0.8; EIA_Code: E96; U/M: EA; AEC Category: Q200; Green_Lifecycle: Active; Green_REACh: Passed
R28 = CRCW06031K00FKEA: RES, 1.00 k, 1%, 0.1 W, 0603; Manufacturer: Vishay-Dale; CompType: Resistor; Value: 1.00k; Res_ohm: 1000; Value_Code: 1k00; Tolerance_%: 1; Power_W: 0.1; Value2: 0.1W; VDC_V: 75; TempCo: 100 ppm/C; SizeArea_mm2: 1.28; SizeX_mm: 1.6; SizeY_mm: 0.8; EIA_Code: E96; U/M: EA; AEC Category: Q200; Green_Lifecycle: Active; Green_REACh: Passed
R29 = CRCW0603499RFKEA: RES, 499, 1%, 0.1 W, 0603; Manufacturer: Vishay-Dale; CompType: Resistor; Value: 499; Value_Code: 499R; Tolerance_%: 1; Power_W: 0.1; Value2: 0.1W; VDC_V: 75; TempCo: 100 ppm/C; SizeArea_mm2: 1.28; SizeX_mm: 1.6; SizeY_mm: 0.8; EIA_Code: E96; U/M: EA; AEC Category: Q200; Green_Lifecycle: Active; Green_REACh: Passed
R30 = CRCW060334K0FKEA: RES, 34.0 k, 1%, 0.1 W, 0603; Manufacturer: Vishay-Dale; CompType: Resistor; Value: 34.0k; Res_ohm: 34000; Value_Code: 34k0; Tolerance_%: 1; Power_W: 0.1; Value2: 0.1W; VDC_V: 75; TempCo: 100 ppm/C; SizeArea_mm2: 1.28; SizeX_mm: 1.6; SizeY_mm: 0.8; EIA_Code: E96; U/M: EA; AEC Category: Q200
R31 = RC0603FR-0712K1L: RES, 12.1 k, 1%, 0.1 W, 0603; Manufacturer: Yageo America; CompType: Resistor; Value: 12.1k; Res_ohm: 12100; Value_Code: 12k1; Tolerance_%: 1; Power_W: 0.1; Value2: 0.1W; VDC_V: 150; TempCo: 200 ppm/C; SizeArea_mm2: 1.28; SizeX_mm: 1.6; SizeY_mm: 0.8; EIA_Code: E96; U/M: EA; AEC Category: Q200; Green_Lifecycle: Active; Green_REACh: Passed
R32 = CRCW0603150KFKEA: RES, 150 k, 1%, 0.1 W, 0603; Manufacturer: Vishay-Dale; CompType: Resistor; Value: 150k; Res_ohm: 150000; Tolerance_%: 1; Power_W: 0.1; Value2: 0.1W; VDC_V: 75; TempCo: 100 ppm/C; SizeArea_mm2: 1.28; SizeX_mm: 1.6; SizeY_mm: 0.8; EIA_Code: E96; U/M: EA; AEC Category: Q200; Green_Lifecycle: Active; Green_REACh: Passed
R33 = CRCW060315K0FKEA: RES, 15.0 k, 1%, 0.1 W, 0603; Manufacturer: Vishay-Dale; CompType: Resistor; Value: 15.0k; Res_ohm: 15000; Value_Code: 15k0; Tolerance_%: 1; Power_W: 0.1; Value2: 0.1W; VDC_V: 75; TempCo: 100 ppm/C; SizeArea_mm2: 1.28; SizeX_mm: 1.6; SizeY_mm: 0.8; EIA_Code: E96; U/M: EA; AEC Category: Q200; Green_Lifecycle: Active; Green_REACh: Passed
R34 = CRCW0603121RFKEA: RES, 121, 1%, 0.1 W, 0603; Manufacturer: Vishay-Dale; CompType: Resistor; Value_Code: 121R; Tolerance_%: 1; Power_W: 0.1; Value2: 0.1W; VDC_V: 75; TempCo: 100 ppm/C; SizeArea_mm2: 1.28; SizeX_mm: 1.6; SizeY_mm: 0.8; EIA_Code: E96; U/M: EA; AEC Category: Q200
R35 = CRCW0603604KFKEA: RES, 604 k, 1%, 0.1 W, 0603; Manufacturer: Vishay-Dale; CompType: Resistor; Value: 604k; Res_ohm: 604000; Tolerance_%: 1; Power_W: 0.1; Value2: 0.1W; VDC_V: 75; TempCo: 100 ppm/C; SizeArea_mm2: 1.28; SizeX_mm: 1.6; SizeY_mm: 0.8; EIA_Code: E96; U/M: EA; AEC Category: Q200; Green_Lifecycle: Active; Green_REACh: Passed
R36 R37 = CRCW0603249KFKEA: RES, 249 k, 1%, 0.1 W, 0603; Manufacturer: Vishay-Dale; CompType: Resistor; Value: 249k; Res_ohm: 249000; Tolerance_%: 1; Power_W: 0.1; Value2: 0.1W; VDC_V: 75; TempCo: 100 ppm/C; SizeArea_mm2: 1.28; SizeX_mm: 1.6; SizeY_mm: 0.8; EIA_Code: E96; U/M: EA; AEC Category: Q200; Green_Lifecycle: Active; Green_REACh: Passed
R38 = CRCW0603124KFKEA: RES, 124 k, 1%, 0.1 W, 0603; Manufacturer: Vishay-Dale; CompType: Resistor; Value: 124k; Res_ohm: 124000; Tolerance_%: 1; Power_W: 0.1; Value2: 0.1W; VDC_V: 75; TempCo: 100 ppm/C; SizeArea_mm2: 1.28; SizeX_mm: 1.6; SizeY_mm: 0.8; EIA_Code: E96; U/M: EA; AEC Category: Q200; Green_Lifecycle: Active; Green_REACh: Passed
R39 = CRCW060347K5FKEA: RES, 47.5 k, 1%, 0.1 W, 0603; Manufacturer: Vishay-Dale; CompType: Resistor; Value: 47.5k; Res_ohm: 47500; Value_Code: 47k5; Tolerance_%: 1; Power_W: 0.1; Value2: 0.1W; VDC_V: 75; TempCo: 100 ppm/C; SizeArea_mm2: 1.28; SizeX_mm: 1.6; SizeY_mm: 0.8; EIA_Code: E96; U/M: EA; AEC Category: Q200; Green_Lifecycle: Active; Green_REACh: Passed
R41 = CRCW060317K4FKEA: RES, 17.4 k, 1%, 0.1 W, 0603; Manufacturer: Vishay-Dale; CompType: Resistor; Value: 17.4k; Res_ohm: 17400; Value_Code: 17k4; Tolerance_%: 1; Power_W: 0.1; Value2: 0.1W; VDC_V: 75; TempCo: 100 ppm/C; SizeArea_mm2: 1.28; SizeX_mm: 1.6; SizeY_mm: 0.8; EIA_Code: E96; U/M: EA; AEC Category: Q200; Green_Lifecycle: Active; Green_REACh: Passed
R42 = CRCW0805100KFKEA: RES, 100 k, 1%, 0.125 W, 0805; Manufacturer: Vishay-Dale; CompType: Resistor; Res_ohm: 100000; Value_Code: 100k; Tolerance_%: 1; Power_W: 0.125; Value2: 0.125W; VDC_V: 150; TempCo: 100 ppm/C; SizeArea_mm2: 2.5; SizeX_mm: 2; SizeY_mm: 1.25; SizeZ_mm: 1.45; EIA_Code: E96; U/M: EA; AEC Category: Q200; Green_Lifecycle: Active; Green_REACh: Passed
RF1 = CRCW25120000Z0EG: RES, 0, 5%, 1 W, AEC-Q200 Grade 0, 2512; Manufacturer: Vishay-Dale; CompType: Resistor; Res_ohm: 0; Value_Code: 0000; Tolerance_%: 5; Power_W: 1; Value2: 1W; TempCo: ppm/C; SizeArea_mm2: 20.16; SizeX_mm: 6.3; SizeY_mm: 3.2; SizeZ_mm: 0.71; EIA_Code: E24; U/M: EA; AEC Category: Q200; AEC Qualified: Y; Green_Lifecycle: Active; Green_REACh: Passed
RT1 = B57237S0479M000: Thermistor NTC, 5 ohm; Manufacturer: TDK; Tolerance_%: 20; Power_W: 3.1; TaMin_C: -55; TaMax_C: 170; SizeAreaWB_mm2: 161.5; SizeArea_mm2: 112.5; SizeX_mm: 15; SizeY_mm: 7.5; SizeZ_mm: 47; U/M: EA
RT2 = NCP18WB473F10RB: Thermistor NTC, 47.0k ohm, 1%, 0603; Manufacturer: MuRata; Tolerance_%: 1; Power_W: 0.1; TaMin_C: -40; TaMax_C: 125; U/M: EA
T1 = CMP-0086589-1: PTH_TRANSFORMER_14; Manufacturer: Wurth Electronics; Ind_H: 120µH; Rsec1_ohm: 0.017; DCR_ohm: 0.24; Ns1toNp: 4:1; AEC Qualified: No; SizeZ_mm: 22.86mm
TP1 TP2 TP5 TP6 = 5000: Test Point, Miniature, Red, TH; Manufacturer: Keystone; CompType: Test Point Loop; ContactFinish: Silver; Green_Lifecycle: Active; Green_REACh: Passed
TP3 TP4 = 1503-2: Terminal, Turret, TH, Double; Manufacturer: Keystone; CompType: Turret Terminal; Green_Lifecycle: Active; Green_REACh: Passed
TP7 = 5001: Test Point, Miniature, Black, TH; Manufacturer: Keystone; CompType: Test Point Loop; ContactFinish: Silver; Green_Lifecycle: Active; Green_REACh: Passed
U1 = CMP-0013005-1: 620-V High-Side Low-Side Gate Driver with 2.5A Peak Output and RobustDrive, D0008A (SOIC-8); Alternate Manufacturer: Texas Instruments; SizeAreaWB_mm2: 56.58; U/M: EA; SizeZ_mm: 1.75; SizeX_mm: 4.9; SizeY_mm: 6.2; SizeArea_mm2: 30.38; CompType: IC
U2 = CMP-0013050-3: High-Frequency Multi-Mode Synchronous Rectifier Controller, DBV0005A (SOT-23-5); Manufacturer: Texas Instruments; Alternate PartNumber: UCC24612-1DBVT; SizeX_mm: 2.8; SizeY_mm: 2.9; CompType: IC; SizeZ_mm: 1.45; SizeArea_mm2: 8.12; SizeAreaWB_mm2: 14.82; AEC Category: Q200; AEC Qualified: N
U3 = CMP-0013027-1: Active-Clamp Flyback Controller, D0016A (SOIC-16); Alternate Manufacturer: Texas Instruments; SizeAreaWB_mm2: 95.2; U/M: EA; SizeZ_mm: 1.75; SizeX_mm: 6; SizeY_mm: 9.9; SizeArea_mm2: 59.4; CompType: IC
U4 = FOD817AS: Optocoupler, 5 kV, 80-160% CTR, SMT; Manufacturer: Fairchild Semiconductor; CTR (Min): 80%; CTR (Max): 160%; Voltage_Isolation_Vrms: 5000V
U5 = CMP-0084731-1: High Bandwidth Low-Iq Programmable Shunt Regulator, DBZ0003A (SOT-23-3); Manufacturer: Texas Instruments; CompType: IC; SizeX_mm: 2.5; AEC Category: Q200; SizeY_mm: 3; SizeArea_mm2: 7.5; AEC Qualified: N; SizeZ_mm: 1.12; SizeAreaWB_mm2: 14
